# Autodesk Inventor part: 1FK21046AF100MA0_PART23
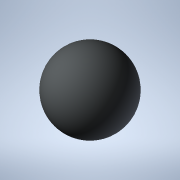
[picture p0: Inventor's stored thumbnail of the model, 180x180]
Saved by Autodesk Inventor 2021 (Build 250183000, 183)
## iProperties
Created: 2025-04
Part Number: 1FK21046AF100MA0_PART23
Material: Generic
Catalog Web Link: www.3dfindit.com
Description: -Servo synchronous motor
Document SubType Name: Modeling
Designer: psAdmin
Mass: 0.137258 g
Surface Area: 1.2868 cm^2
Volume: 0.137258 cm^3
Density: 1 g/cm^3
Appearance: PSOLRGB-212-217-219
Category: PARTsolutions
Title: 1FK21046AF100MA0_PART23
Author: Cadenas PARTsolutions
Comments: Servo synchronous motor
Sending System: PARTsolutions
Preprocessor: ST-DEVELOPER v19.3
PSOL_IDENT_0: {$CADENAS_DATA/23d-libs/siemens_ag/_cat_/4f/2b/1fk21046af100ma0.prj},216 {VTYP=3D},{NB=1FK21046AF100
PSOL_IDENT_1: MA0_PART23},{LINA=1FK21046AF100MA0_PART23},{NN=1FK21046AF100MA0_PART23},{NOPRJ=TRUE},{DATE=19.08.202
PSOL_IDENT_2: 5 14:00:37},{GEOMDATE=30.07.2025 02:01:06},{VERSION=},{LINEID=10},{WBVAR=},{WBNUMERIC=}  {NB=1FK2104
PSOL_IDENT_3: 6AF100MA0_PART23},{LINA=1FK21046AF100MA0_PART23},{KT=DUMMY},{PREVIEW=../../../_pool_/cb/72/p_d211_xx
PSOL_IDENT_4: _00434j.png},{DESCSHORT=SIMOTICS S-1FK2 HD, SINAMICS S210 3AC 400V-480V, 3.2 Nm, 3000 rpm},{DESCLONG=
PSOL_IDENT_5: SIMOTICS S-1FK2 HD servo motor M0=3.2 Nm; PN = 1 kW at nN=3000 rpm (380-480 V); PN = 0.5 kW at nN=15
PSOL_IDENT_6: 00 rpm (200-240 V); with holding brake; degree of protection IP64; cylindrical shaft D19x40mm; absol
PSOL_IDENT_7: ute encoder 22-bit + 12-bit multiturn (encoder AM22DQC); with OCC interface; plug size M17, rotatabl
PSOL_IDENT_8: e; SIMOTICS S-1FK2 servomotorfor a wide range of uses in industrial environments. SIMOTICS S‑1FK2 se
PSOL_IDENT_9: rvomotors are compact synchronous motors with a high dynamic performance that set themselves apart a
PSOL_IDENT_10: s a result of their high power density, degree of protection and overload capability. The motors are
PSOL_IDENT_11: available in two variants: as High Dynamic variant (highest dynamic performance as a result of the
PSOL_IDENT_12: low intrinsic moment of inertia for applications demanding a high dynamic performance with low moved
PSOL_IDENT_13: masses) - and as Compact variant (precise and stable closed-loop control for medium up to large mov
PSOL_IDENT_14: ed masses as a result of a medium intrinsic moment of inertia). SIMOTICSS‑1FK2 servomotors fully exp
PSOL_IDENT_15: loit their strengths in a system with the SINAMICSS210 frequency converter and simple connection usi
PSOL_IDENT_16: ng the one cable connection (OCC). Advantages include the short control and positioning times, fast
PSOL_IDENT_17: and precise correction of disturbing quantities as well as stable control with a high dynamic perfor
PSOL_IDENT_18: mance. The servo motors can be configured to address a wide range of requirements. For example with
PSOL_IDENT_19: and without holding brake, IP64 or IP65 degree of protection, singleturn or multiturn absolute encod
PSOL_IDENT_20: ers - to name just a few. Further, the servomotors are available in different shaft heights extendin
PSOL_IDENT_21: g from 20 to 100. A shaft sealing ring is available to achieve an IP65 degree of protection and for
PSOL_IDENT_22: subsequent mounting at the motor or as spare part. SIMOTICS - the optimum motor for each and every m
PSOL_IDENT_23: otion control application.},{INTNO=195125049673},{SUPPLIERALTNO=1FK2104-6AF10-0MA0},{MANUID=1FK21046
PSOL_IDENT_24: AF100MA0},{MANUNAME=Siemens},{MANUTYPEDESC=Synchronous motor 1FK2-HD 3.2 NM},{AAU732=SIMOTICS},{AAO0
PSOL_IDENT_25: 57=S-1FK2},{AAU734=SIMOTICS S-1FK2 HD servo motor M0=3.2 Nm; PN = 1 kW at nN=3000 rpm (380-480 V); P
PSOL_IDENT_26: N = 0.5 kW at nN=1500 rpm (200-240 V); with holding brake; degree of protection IP64; cylindrical sh
PSOL_IDENT_27: aft D19x40mm; absolute encoder 22-bit + 12-bit multiturn (encoder AM22DQC); with OCC interface; plug
PSOL_IDENT_28: size M17, rotatable;},{AAW338=Synchronous motor 1FK2-HD 3.2 NM},{AAO742=SIMOTICS},{AAO663=404294869
PSOL_IDENT_29: 4534},{NOCUPEROU=1},{PRICEQUANTITY=1},{QUANTITYMIN=1},{QUANTITYINT=1},{CTN=85015220},{COO=DE},{AAO67
PSOL_IDENT_30: 6=1FK2104-6AF10-0MA0},{AAO677=Siemens AG},{ORDERUNIT=C62},{CONTENTUNIT=C62}
NB: 1FK21046AF100MA0_PART23
NT: Servo synchronous motor
NBSYN: $MANUID._PART23
LINA: 1FK21046AF100MA0_PART23
CATALOG: SIEMENS
PREVIEW: ../../../_pool_/cb/72/p_d211_xx_00434j.png
DESCSHORT: SIMOTICS S-1FK2 HD, SINAMICS S210 3AC 400V-480V, 3.2 Nm, 3000 rpm
DESCLONG: SIMOTICS S-1FK2 HD servo motor M0=3.2 Nm; PN = 1 kW at nN=3000 rpm (380-480 V); PN = 0.5 kW at nN=1500 rpm (200-240 V); with holding brake; degree of protection
INTNO: 195125049673
SUPPLIERALTNO: 1FK2104-6AF10-0MA0
MANUID: 1FK21046AF100MA0
MANUNAME: Siemens
MANUTYPEDESC: Synchronous motor 1FK2-HD 3.2 NM
AAU732: SIMOTICS
AAO057: S-1FK2
AAU734: SIMOTICS S-1FK2 HD servo motor M0=3.2 Nm; PN = 1 kW at nN=3000 rpm (380-480 V); PN = 0.5 kW at nN=1500 rpm (200-240 V); with holding brake; degree of protection
AAW338: Synchronous motor 1FK2-HD 3.2 NM
AAO742: SIMOTICS
AAO663: 4042948694534.0
NOCUPEROU: 1
PRICEQUANTITY: 1
QUANTITYMIN: 1
QUANTITYINT: 1
CTN: 85015220
COO: DE
ARTICLENO: 1FK21046AF100MA0_PART23
BOMINFO: 1FK21046AF100MA0_PART23
CREATOR: CADENAS GmbH
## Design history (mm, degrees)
feature "2025_04_17_14_59_39_0177"
body "Solid1"
